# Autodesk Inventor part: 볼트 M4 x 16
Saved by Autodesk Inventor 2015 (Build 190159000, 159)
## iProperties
Created: 2025-08
Part Number: 볼트 M4 x 16
Material: 일반
Document SubType Name: Modeling
Designer: USER
Density: 1 g/cm^3
Appearance: 기본값
Author: jhkim
Description: 6각 소켓 머리 캡 나사
Creation Date: 2025-08-05
Sending System: Autodesk Inventor 2026
Preprocessor: ST-DEVELOPER v20.1
Author: USER
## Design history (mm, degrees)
node "볼트 M4 x 161"
body "Solid1"
node "기준1"
